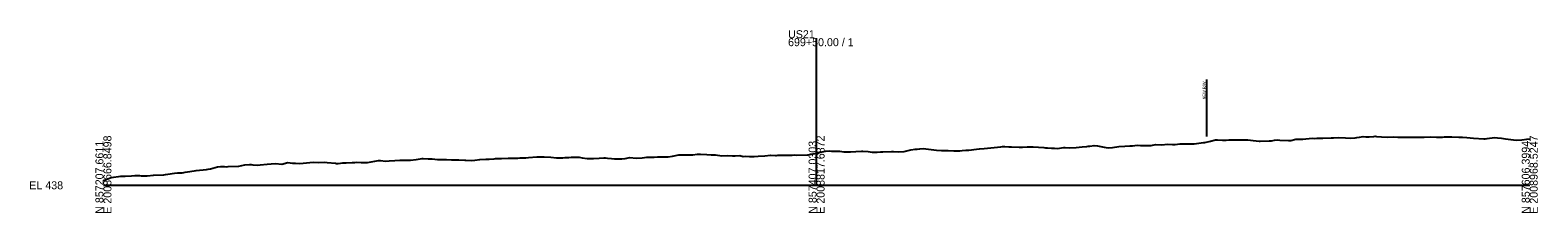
# Model space of a CAD drawing. Extents: x 2008702 to 2066449, y 841632 to 857812.
# Drawn here: x 2062921 to 2063449, y 844204 to 844268 of the extents above; entities that cross this region are included whole.
import ezdxf

# ---------------------------------------------------------------- set-up
doc = ezdxf.new("R2010")
doc.units = 0
for name, color, linetype in [('RD_GPK_XS_Cell', 7, 'Continuous'), ('RD_XS_ExGround', 7, 'Continuous'), ('RD_XS_TX_Box', 7, 'Continuous'), ('RD_XS_TX_Elev_EX', 7, 'Continuous')]:
    doc.layers.add(name, color=color, linetype=linetype)

msp = doc.modelspace()

# ---------------------------------------------------------------- linework, layer by layer
at = {"layer": 'RD_GPK_XS_Cell'}
for p, q in [((2063196.51, 844213.53), (2063196.51, 844265.18)), ((2062946.51, 844213.53), (2063196.51, 844213.53)), ((2063196.51, 844213.53), (2063446.51, 844213.53))]:
    msp.add_line(p, q, dxfattribs=at)
at = {"layer": 'RD_XS_ExGround'}
msp.add_lwpolyline([(2062946.51, 844215.29), (2062946.85, 844215.29), (2062949.2, 844216.26), (2062952.59, 844216.77), (2062954.18, 844216.74), (2062956.35, 844216.8), (2062957.56, 844216.93), (2062959.15, 844216.92), (2062959.7, 844216.89), (2062960.11, 844216.9), (2062961.84, 844216.8), (2062964.12, 844217.1), (2062967.64, 844217.24), (2062968.27, 844217.36), (2062969.1, 844217.45), (2062971.4, 844217.74), (2062972.55, 844217.92), (2062974.07, 844217.96), (2062974.69, 844218.03), (2062975.16, 844218.09), (2062976.84, 844218.33), (2062979.04, 844218.69), (2062982.69, 844219.05), (2062983.26, 844219.14), (2062984.02, 844219.35), (2062986.45, 844220.01), (2062987.55, 844220.12), (2062988.99, 844220.09), (2062989.69, 844220.05), (2062990.21, 844220.13), (2062993.98, 844220.23), (2062996.11, 844220.7), (2062997.74, 844220.8), (2062998.25, 844220.8), (2062998.94, 844220.73), (2063000.4, 844220.63), (2063001.5, 844220.71), (2063003.91, 844220.97), (2063005.26, 844221.06), (2063006.82, 844221.16), (2063009.03, 844220.9), (2063011.11, 844221.57), (2063012.79, 844221.32), (2063013.25, 844221.33), (2063013.86, 844221.31), (2063015.39, 844221.24), (2063016.55, 844221.34), (2063018.83, 844221.59), (2063020.31, 844221.6), (2063021.82, 844221.55), (2063024.08, 844221.63), (2063024.93, 844221.53), (2063027.84, 844221.26), (2063028.24, 844221.23), (2063028.78, 844221.24), (2063030.38, 844221.47), (2063031.6, 844221.46), (2063033.75, 844221.51), (2063034.67, 844221.58), (2063035.37, 844221.63), (2063036.81, 844221.59), (2063039.13, 844221.57), (2063040.39, 844221.76), (2063042.89, 844222.2), (2063043.24, 844222.22), (2063043.69, 844222.18), (2063045.38, 844222.04), (2063046.65, 844222.13), (2063048.67, 844222.28), (2063050.42, 844222.3), (2063051.8, 844222.31), (2063053.64, 844222.32), (2063054.18, 844222.32), (2063056.09, 844222.53), (2063058.23, 844222.93), (2063058.61, 844222.95), (2063060.37, 844222.85), (2063061.7, 844222.84), (2063063.59, 844222.62), (2063065.47, 844222.56), (2063066.8, 844222.55), (2063068.56, 844222.5), (2063069.23, 844222.52), (2063071.08, 844222.52), (2063073.22, 844222.39), (2063073.53, 844222.36), (2063075.37, 844222.25), (2063076.75, 844222.32), (2063078.51, 844222.57), (2063080.52, 844222.65), (2063081.79, 844222.76), (2063083.48, 844222.82), (2063083.93, 844222.89), (2063084.28, 844222.92), (2063086.08, 844222.89), (2063088.45, 844223.05), (2063090.36, 844223.1), (2063091.8, 844223.1), (2063092.5, 844223.12), (2063093.43, 844223.19), (2063094.64, 844223.23), (2063095.57, 844223.3), (2063098.4, 844223.49), (2063099.33, 844223.55), (2063101.07, 844223.53), (2063103.37, 844223.42), (2063105.35, 844223.13), (2063106.85, 844223.22), (2063107.5, 844223.19), (2063108.35, 844223.33), (2063109.64, 844223.3), (2063110.62, 844223.46), (2063113.32, 844223.35), (2063114.38, 844223.23), (2063116.06, 844222.9), (2063118.29, 844222.95), (2063120.35, 844223.04), (2063121.9, 844223.16), (2063122.49, 844223.17), (2063123.26, 844223.08), (2063124.63, 844222.93), (2063125.67, 844222.87), (2063128.24, 844222.86), (2063129.43, 844222.91), (2063131.06, 844223.24), (2063133.21, 844223.01), (2063135.34, 844223.18), (2063136.95, 844223.42), (2063137.48, 844223.44), (2063138.18, 844223.45), (2063139.63, 844223.43), (2063140.72, 844223.51), (2063143.16, 844223.57), (2063144.48, 844223.58), (2063146.05, 844223.77), (2063148.24, 844224.26), (2063150.34, 844224.22), (2063152, 844224.24), (2063152.48, 844224.27), (2063153.1, 844224.27), (2063154.62, 844224.41), (2063155.77, 844224.45), (2063158.08, 844224.35), (2063159.53, 844224.24), (2063161.05, 844224.18), (2063163.29, 844223.82), (2063165.33, 844224.01), (2063167.05, 844223.84), (2063167.47, 844223.87), (2063168.02, 844223.82), (2063169.61, 844223.94), (2063170.82, 844223.68), (2063171.76, 844223.74), (2063173, 844223.66), (2063173.9, 844223.69), (2063174.58, 844223.65), (2063176.04, 844223.8), (2063178.34, 844223.82), (2063180.32, 844224.08), (2063182.1, 844224.02), (2063182.47, 844224.04), (2063182.94, 844224.07), (2063184.61, 844224.13), (2063185.87, 844224.16), (2063186.75, 844224.16), (2063187.92, 844224.15), (2063188.89, 844224.2), (2063189.63, 844224.16), (2063193.39, 844224.28), (2063195.32, 844224.56), (2063196.51, 844224.83), (2063197.15, 844224.97), (2063197.46, 844225), (2063197.86, 844225.16), (2063199.6, 844225.52), (2063200.92, 844225.62), (2063201.74, 844225.5), (2063202.84, 844225.55), (2063203.89, 844225.52), (2063204.68, 844225.49), (2063206.03, 844225.33), (2063207.81, 844225.25), (2063208.44, 844225.26), (2063210.31, 844225.42), (2063212.2, 844225.55), (2063212.78, 844225.54), (2063214.6, 844225.43), (2063215.97, 844225.19), (2063216.74, 844225.11), (2063217.75, 844225.14), (2063218.88, 844225.24), (2063219.73, 844225.25), (2063222.73, 844225.4), (2063223.16, 844225.45), (2063223.49, 844225.39), (2063225.31, 844225.28), (2063227.26, 844225.42), (2063227.7, 844225.51), (2063229.59, 844225.95), (2063231.02, 844226.24), (2063231.73, 844226.2), (2063232.67, 844226.35), (2063233.87, 844226.45), (2063234.78, 844226.37), (2063237.65, 844225.94), (2063238.54, 844225.86), (2063240.3, 844225.75), (2063242.62, 844225.72), (2063244.58, 844225.61), (2063246.07, 844225.59), (2063246.72, 844225.65), (2063247.59, 844225.73), (2063248.87, 844225.88), (2063249.83, 844225.9), (2063252.57, 844226.19), (2063253.59, 844226.32), (2063255.29, 844226.49), (2063257.54, 844226.65), (2063261.12, 844227.08), (2063261.72, 844227.14), (2063262.51, 844227.15), (2063263.86, 844227.06), (2063264.88, 844227.08), (2063267.49, 844226.9), (2063268.64, 844226.87), (2063270.29, 844227.05), (2063272.46, 844227.02), (2063276.17, 844226.75), (2063276.71, 844226.72), (2063277.43, 844226.66), (2063278.85, 844226.59), (2063279.93, 844226.51), (2063281, 844226.5), (2063282.41, 844226.68), (2063283.14, 844226.78), (2063283.69, 844226.79), (2063285.28, 844226.71), (2063287.46, 844226.83), (2063289.56, 844226.98), (2063291.22, 844227.13), (2063291.71, 844227.21), (2063292.35, 844227.27), (2063293.85, 844227.47), (2063294.98, 844227.34), (2063297.32, 844226.91), (2063298.74, 844226.7), (2063300.27, 844226.85), (2063302.51, 844227.11), (2063304.56, 844227.32), (2063306.27, 844227.37), (2063306.7, 844227.44), (2063307.27, 844227.44), (2063308.84, 844227.59), (2063310.03, 844227.52), (2063312.24, 844227.47), (2063313.79, 844227.53), (2063315.27, 844227.81), (2063317.56, 844227.74), (2063319.55, 844227.94), (2063321.32, 844227.91), (2063321.69, 844227.9), (2063322.19, 844227.9), (2063323.84, 844228.06), (2063325.08, 844228.07), (2063325.98, 844228.11), (2063327.16, 844228.05), (2063328.12, 844228.1), (2063328.84, 844228.1), (2063332.14, 844228.5), (2063332.61, 844228.57), (2063334.55, 844228.97), (2063336.37, 844229.45), (2063336.69, 844229.5), (2063337.11, 844229.52), (2063338.83, 844229.41), (2063340.13, 844229.42), (2063340.97, 844229.45), (2063342.08, 844229.45), (2063343.11, 844229.47), (2063343.89, 844229.46), (2063347.06, 844229.51), (2063347.66, 844229.48), (2063349.54, 844229.24), (2063351.68, 844229.06), (2063352.03, 844229.08), (2063355.18, 844229.1), (2063355.97, 844229.13), (2063357, 844229.33), (2063358.11, 844229.46), (2063358.94, 844229.42), (2063361.98, 844229.23), (2063362.71, 844229.31), (2063364.53, 844229.74), (2063366.95, 844229.75), (2063370.23, 844230.07), (2063370.96, 844229.97), (2063371.92, 844230.04), (2063373.1, 844230.12), (2063373.99, 844230.1), (2063376.9, 844230.17), (2063377.76, 844230.24), (2063379.53, 844230.27), (2063381.87, 844230.21), (2063383.81, 844230.11), (2063385.28, 844230.19), (2063385.95, 844230.26), (2063386.84, 844230.42), (2063388.1, 844230.62), (2063389.04, 844230.55), (2063390.24, 844230.6), (2063391.81, 844230.69), (2063392.38, 844230.75), (2063392.81, 844230.72), (2063394.52, 844230.6), (2063396.79, 844230.47), (2063398.81, 844230.51), (2063400.33, 844230.46), (2063400.95, 844230.4), (2063401.76, 844230.39), (2063403.09, 844230.45), (2063404.1, 844230.4), (2063406.73, 844230.42), (2063407.86, 844230.44), (2063409.52, 844230.46), (2063411.71, 844230.5), (2063413.8, 844230.44), (2063415.38, 844230.46), (2063415.94, 844230.42), (2063416.68, 844230.53), (2063418.08, 844230.58), (2063419.15, 844230.57), (2063421.65, 844230.48), (2063422.37, 844230.42), (2063422.91, 844230.41), (2063424.51, 844230.32), (2063426.81, 844230.1), (2063430.43, 844229.8), (2063430.94, 844229.85), (2063431.6, 844229.94), (2063434.2, 844230.26), (2063435.22, 844230.22), (2063436.57, 844230.05), (2063437.36, 844229.93), (2063437.96, 844229.88), (2063441.72, 844229.38), (2063443.79, 844229.46), (2063445.48, 844229.73), (2063446.51, 844229.79)], dxfattribs=at)
at = {"layer": 'RD_XS_TX_Box'}
msp.add_line((2063333.15, 844250.68), (2063333.15, 844230.68), dxfattribs=at)

# ---------------------------------------------------------------- texts
at = {"layer": 'RD_GPK_XS_Cell'}
for s, p in [('US21', (2063186.51, 844265.18)), ('699+50.00 / 1', (2063186.51, 844262.38)), ('EL 438', (2062920.51, 844212.13))]:
    msp.add_text(s, height=2.8, dxfattribs=at).set_placement(p)
for s, p in [('E 2008666.8498', (2062949.31, 844203.53)), ('E 2008817.6872', (2063199.31, 844203.53)), ('E 2008968.5247', (2063449.31, 844203.53)), ('N 857207.6611', (2062946.51, 844203.53)), ('N 857407.0303', (2063196.51, 844203.53)), ('N 857606.3994', (2063446.51, 844203.53))]:
    msp.add_text(s, height=2.8, rotation=90, dxfattribs=at).set_placement(p)
at = {"layer": 'RD_XS_TX_Box'}
msp.add_text('NEW R/W', height=1, rotation=90, dxfattribs=at).set_placement((2063332.9, 844243.68))
at = {"layer": 'RD_XS_TX_Elev_EX'}
msp.add_text('443.65', height=0.8, rotation=90, dxfattribs=at).set_placement((2063196.91, 844217.37))

doc.saveas('drawing.dxf')
